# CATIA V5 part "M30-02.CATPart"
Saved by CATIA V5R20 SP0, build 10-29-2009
Part number: M30-02
Revision: ANY
Definition: UNKNOWN
Nomenclature: M30-02
Source: Unknown
Bounding box of the stored display mesh (mm): x -19 to 19, y -18.807 to 18.807, z 0 to 170
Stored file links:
  C:\Users\Utente\Desktop\IO LAVORO\3D X SITO CF\X 3D SITO CF 27-09-2020\740T\740T-30\M30-02.CATPart
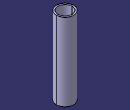
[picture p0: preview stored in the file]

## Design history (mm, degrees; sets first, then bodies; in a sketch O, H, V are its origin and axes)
Body1 "NONE" (main body)
  Solid1: solid without history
